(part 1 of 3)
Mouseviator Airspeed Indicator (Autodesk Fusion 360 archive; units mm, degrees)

design "Mouseviator Airspeed Indicator" references "X27.168 Stepper", "Instrument Bezel and Glass MS33638C"
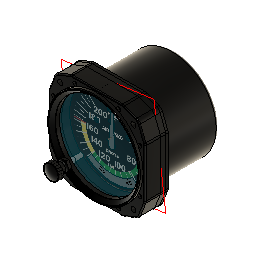
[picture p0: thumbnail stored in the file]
description: Spur Gear; Module: 2.0; Num Teeth: 30; Pressure Angle: 20.0; Backlash: 0.00 mm
parameter "NeedleFit" = 0.1
parameter "RotateTol" = 0.2
parameter "PressFit" = 0.1
parameter "KnobRodThick" = 4
parameter "ElephantFoot" = 0.5
parameter "GearGrow" = 0.15
external_derived "ExternalDerived1" bodies "Airspeed Bezel"
component_insert "Component Insert"
base_feature "Base Feature1"
position "Position1"
remove_instance "RemoveInstance10"
sketch "Sketch3" plane through (0, 2, 0) normal (0, 1, 0) x axis (-1, 0, 0)
  line L1 (41.1157, 22.3885) -> (36.4994, 34.1766)
  line L2 (41.4655, -20.5361) -> (41.4655, 20.5361)
  line L3 (36.4994, -34.1766) -> (41.1157, -22.3885)
  line L4 (23.2139, -41.1177) -> (33.6166, -37.0564)
  line L5 (-21.3665, -41.4655) -> (21.3665, -41.4655)
  line L6 (-33.6166, -37.0564) -> (-23.2139, -41.1177)
  line L7 (-41.1157, -22.3885) -> (-36.4994, -34.1766)
  line L8 (-41.4655, 20.5361) -> (-41.4655, -20.5361)
  line L9 (-36.4994, 34.1766) -> (-41.1157, 22.3885)
  line L10 (-23.2139, 41.1177) -> (-33.6166, 37.0564)
  line L11 (21.3665, 41.4655) -> (-21.3665, 41.4655)
  line L12 (33.6166, 37.0564) -> (23.2139, 41.1177)
  circle C1 centre (0, 0) radius 2.4
  circle C2 centre (-36.96, 18.76) radius 0.9
  circle C3 centre (-18.76, -36.96) radius 0.9
  circle C4 centre (36.96, -18.76) radius 0.9
  circle C5 centre (18.76, 36.96) radius 0.9
  circle C6 centre (36.96, 18.76) radius 0.9
  circle C7 centre (18.76, -36.96) radius 0.9
  circle C8 centre (-36.96, -18.76) radius 0.9
  circle C9 centre (-18.76, 36.96) radius 0.9
  arc A1 centre (36.3855, 20.5361) radius 5.08 clockwise from (41.1157, 22.3885) to (41.4655, 20.5361)
  arc A2 centre (36.3855, -20.5361) radius 5.08 clockwise from (41.4655, -20.5361) to (41.1157, -22.3885)
  arc A3 centre (31.7692, -32.3242) radius 5.08 clockwise from (36.4994, -34.1766) to (33.6166, -37.0564)
  arc A4 centre (21.3665, -36.3855) radius 5.08 clockwise from (23.2139, -41.1177) to (21.3665, -41.4655)
  arc A5 centre (-21.3665, -36.3855) radius 5.08 clockwise from (-21.3665, -41.4655) to (-23.2139, -41.1177)
  arc A6 centre (-31.7692, -32.3242) radius 5.08 clockwise from (-33.6166, -37.0564) to (-36.4994, -34.1766)
  arc A7 centre (-36.3855, -20.5361) radius 5.08 clockwise from (-41.1157, -22.3885) to (-41.4655, -20.5361)
  arc A8 centre (-36.3855, 20.5361) radius 5.08 clockwise from (-41.4655, 20.5361) to (-41.1157, 22.3885)
  arc A9 centre (-31.7692, 32.3242) radius 5.08 clockwise from (-36.4994, 34.1766) to (-33.6166, 37.0564)
  arc A10 centre (-21.3665, 36.3855) radius 5.08 clockwise from (-23.2139, 41.1177) to (-21.3665, 41.4655)
  arc A11 centre (21.3665, 36.3855) radius 5.08 clockwise from (21.3665, 41.4655) to (23.2139, 41.1177)
  arc A12 centre (31.7692, 32.3242) radius 5.08 clockwise from (33.6166, 37.0564) to (36.4994, 34.1766)
  circle C10 centre (-31.4309, 31.4309) radius 2.159
  circle C11 centre (31.4309, -31.4309) radius 2.159
  circle C12 centre (31.4309, 31.4309) radius 2.159
  circle C13 centre (-31.4309, -31.4309) radius 2.159
  circle C14 centre (0, 0) radius 35.5256
  concentric C1 C14
  dimension "d246" diameter C1 = 4.8
extrude "Extrude1" new body sketch "Sketch3" along normal blind 4.5
decal "Decal1"
decal "Decal2"
sketch "Sketch2" plane through (0, 2, 0) normal (0, -1, 0) x axis (1, 0, 0)
  line L1 (-41.129, -18.2913) -> (-41.129, 18.2913)
  line L2 (-36.3113, -33.5274) -> (-40.8669, -19.9021)
  line L3 (-19.078, -41.1949) -> (-33.0328, -36.7577)
  line L4 (17.5387, -41.4337) -> (-17.5387, -41.4337)
  line L5 (33.0328, -36.7577) -> (19.078, -41.1949)
  line L6 (40.8669, -19.9021) -> (36.3113, -33.5274)
  line L7 (41.129, 18.2913) -> (41.129, -18.2913)
  line L8 (36.3113, 33.5274) -> (40.8669, 19.9021)
  line L9 (19.078, 41.1949) -> (33.0328, 36.7577)
  line L10 (-17.5387, 41.4337) -> (17.5387, 41.4337)
  line L11 (-33.0328, 36.7577) -> (-19.078, 41.1949)
  line L12 (-40.8669, 19.9021) -> (-36.3113, 33.5274)
  line L13 (-9, 5.3277) -> (-9, 3.4858)
  line L14 (-9, 5.3393) -> (-9, 3.4741)
  line L15 (-41.4655, -20.5361) -> (-41.4655, 20.5361)
  line L16 (-36.4994, -34.1766) -> (-41.1157, -22.3885)
  line L17 (-23.2139, -41.1177) -> (-33.6166, -37.0564)
  line L18 (21.3665, -41.4655) -> (-21.3665, -41.4655)
  line L19 (33.6166, -37.0564) -> (23.2139, -41.1177)
  line L20 (41.1157, -22.3885) -> (36.4994, -34.1766)
  line L21 (41.4655, 20.5361) -> (41.4655, -20.5361)
  line L22 (36.4994, 34.1766) -> (41.1157, 22.3885)
  line L23 (23.2139, 41.1177) -> (33.6166, 37.0564)
  line L24 (-21.3665, 41.4655) -> (21.3665, 41.4655)
  line L25 (-33.6166, 37.0564) -> (-23.2139, 41.1177)
  line L26 (-41.1157, 22.3885) -> (-36.4994, 34.1766)
  circle C1 centre (-31.4309, -31.4309) radius 2.159
  circle C2 centre (-31.4309, 31.4309) radius 2.159
  circle C3 centre (31.4309, 31.4309) radius 2.159
  circle C4 centre (0, 0) radius 1.25
  circle C5 centre (31.4309, -31.4309) radius 2.159
  arc A1 centre (-36.049, 18.2913) radius 5.08 clockwise from (-41.129, 18.2913) to (-40.8669, 19.9021)
  arc A2 centre (-36.049, -18.2913) radius 5.08 clockwise from (-40.8669, -19.9021) to (-41.129, -18.2913)
  arc A3 centre (-31.4935, -31.9166) radius 5.08 clockwise from (-33.0328, -36.7577) to (-36.3113, -33.5274)
  arc A4 centre (-17.5387, -36.3537) radius 5.08 clockwise from (-17.5387, -41.4337) to (-19.078, -41.1949)
  arc A5 centre (17.5387, -36.3537) radius 5.08 clockwise from (19.078, -41.1949) to (17.5387, -41.4337)
  arc A6 centre (31.4935, -31.9166) radius 5.08 clockwise from (36.3113, -33.5274) to (33.0328, -36.7577)
  arc A7 centre (36.049, -18.2913) radius 5.08 clockwise from (41.129, -18.2913) to (40.8669, -19.9021)
  arc A8 centre (36.049, 18.2913) radius 5.08 clockwise from (40.8669, 19.9021) to (41.129, 18.2913)
  arc A9 centre (31.4935, 31.9166) radius 5.08 clockwise from (33.0328, 36.7577) to (36.3113, 33.5274)
  arc A10 centre (17.5387, 36.3537) radius 5.08 clockwise from (17.5387, 41.4337) to (19.078, 41.1949)
  arc A11 centre (-17.5387, 36.3537) radius 5.08 clockwise from (-19.078, 41.1949) to (-17.5387, 41.4337)
  arc A12 centre (-31.4935, 31.9166) radius 5.08 clockwise from (-36.3113, 33.5274) to (-33.0328, 36.7577)
  circle C6 centre (-2.3097, 10.9434) radius 1
  circle C7 centre (-18.76, 36.96) radius 0.9
  circle C8 centre (31.4309, -31.4309) radius 2.159
  circle C9 centre (-31.4309, 31.4309) radius 2.159
  circle C10 centre (31.4309, 31.4309) radius 2.159
  circle C11 centre (36.96, -18.76) radius 0.9
  circle C12 centre (-36.96, 18.76) radius 0.9
  circle C13 centre (-18.76, -36.96) radius 0.9
  circle C14 centre (18.76, -36.96) radius 0.9
  circle C15 centre (-31.4309, -31.4309) radius 2.159
  circle C16 centre (36.96, 18.76) radius 0.9
  circle C17 centre (-36.96, -18.76) radius 0.9
  circle C18 centre (18.76, 36.96) radius 0.9
  arc A13 centre (-36.3855, 20.5361) radius 5.08 clockwise from (-41.4655, 20.5361) to (-41.1157, 22.3885)
  arc A14 centre (-36.3855, -20.5361) radius 5.08 clockwise from (-41.1157, -22.3885) to (-41.4655, -20.5361)
  arc A15 centre (-31.7692, -32.3242) radius 5.08 clockwise from (-33.6166, -37.0564) to (-36.4994, -34.1766)
  arc A16 centre (-21.3665, -36.3855) radius 5.08 clockwise from (-21.3665, -41.4655) to (-23.2139, -41.1177)
  arc A17 centre (21.3665, -36.3855) radius 5.08 clockwise from (23.2139, -41.1177) to (21.3665, -41.4655)
  arc A18 centre (31.7692, -32.3242) radius 5.08 clockwise from (36.4994, -34.1766) to (33.6166, -37.0564)
  arc A19 centre (36.3855, -20.5361) radius 5.08 clockwise from (41.4655, -20.5361) to (41.1157, -22.3885)
  arc A20 centre (36.3855, 20.5361) radius 5.08 clockwise from (41.1157, 22.3885) to (41.4655, 20.5361)
  arc A21 centre (31.7692, 32.3242) radius 5.08 clockwise from (33.6166, 37.0564) to (36.4994, 34.1766)
  arc A22 centre (21.3665, 36.3855) radius 5.08 clockwise from (21.3665, 41.4655) to (23.2139, 41.1177)
  arc A23 centre (-21.3665, 36.3855) radius 5.08 clockwise from (-23.2139, 41.1177) to (-21.3665, 41.4655)
  arc A24 centre (-31.7692, 32.3242) radius 5.08 clockwise from (-36.4994, 34.1766) to (-33.6166, 37.0564)
  circle C19 centre (0, 0) radius 2.4
  dimension "d43" diameter C6 = 2
position "Position8"
joint "Assemble2" alignAngle 0 alignOffsetX 0 alignOffsetY 0 alignOffsetZ 0
base_feature "Base Feature1"
joint "Assemble4" alignAngle -90 alignOffsetX 0 alignOffsetY 0 alignOffsetZ -0.4
work_plane "WorkPlane1" AlongDistance 1.5
canvas "Canvas1"
sketch "Sketch1" plane through (0, 0.5, 0) normal (0, -1, 0) x axis (-1, 0, 0)
  line L1 (-6.6247, 4.1349) -> (-5.7667, 7.3554)
  line L2 (17.0612, -22.1649) -> (-6.6247, 4.1349)
  line L3 (17.2564, -22.0118) -> (-6.5518, 8.3569)
  line L4 (-2.4344, 7.42) -> (-5.7667, 7.3554)
  line L5 (17.4516, -21.8588) -> (-2.4344, 7.42)
  line L6 (17.4516, -21.8588) -> (17.0612, -22.1649)
  line L7 (-2.0946, -0.8951) -> (-1.3853, 1.7668)
  line L8 (1.3689, 1.8201) -> (-1.3853, 1.7668)
  circle C1 centre (0, 0) radius 0.5
  circle C2 centre (0, 0) radius 0.55
  point P3 (-6.6247, 4.1349)
  point P6 (-2.4344, 7.42)
  point P4 (17.0612, -22.1649)
  point P7 (17.4516, -21.8588)
  point P5 (17.2564, -22.0118)
  point P9 (-1.3853, 1.7668)
  point P10 (-2.0946, -0.8951)
  point P11 (-1.3853, 1.7668)
  point P12 (1.3689, 1.8201)
  point P14 (-5.7667, 7.3554)
  symmetric P3 L3 P6
  symmetric P4 L3 P7
  midpoint P5 L6
  perpendicular L3 L6
  coincident L3 P9
  coincident L2 P10
  parallel L1 L7
  symmetric L3 P9 P11
  symmetric L3 P10 P12
  concentric C1 C2
  coincident L3 P14
  dimension "d55" distance C1 C2 = 0.05 (= "NeedleFit / 2")
extrude "Extrude1" new body sketch "Sketch1" profile of L1 L2 L4 L5 L6 C1 L7 L8 C2 along normal blind 1
extrude "Extrude2" cut sketch "Sketch2" profile of C6 to an object
fillet "Fillet1" radius 0.5 0.25
decal "Decal3"
copy_paste "CutPaste3"
copy_paste "CutPaste4"
sketch "Sketch2" plane through (0, 0.5, 0) normal (0, 1, 0) x axis (-1, 0, 0)
  line L1 (-5.7667, -7.3554) -> (-6.6247, -4.1349)
  line L2 (-2.4344, -7.42) -> (-5.7667, -7.3554)
  line L3 (17.4516, 21.8588) -> (-2.4344, -7.42)
  line L4 (17.0612, 22.1649) -> (17.4516, 21.8588)
  line L5 (-6.6247, -4.1349) -> (17.0612, 22.1649)
  circle C1 centre (0, 0) radius 2
  circle C2 centre (0, 0) radius 0.8
  circle C3 centre (0, 0) radius 0.5
  point P1 (0, 0)
  point P7 (0, 0)
  coincident P1 P7
  concentric C1 C2
  dimension "d51" diameter C1 = 4
  dimension "d266" distance C2 C3 = 0.3
extrude "Extrude2" add sketch "Sketch2" profile of C1 C2 to an object
ground "Ground1"
canvas "Canvas1"
position "Position4"
sketch "Window" plane through (0, 2, 0) normal (0, -1, 0) x axis (1, 0, 0)
  line L1 (22.1762, -26.4285) -> (17.6767, -21.0662)
  line L2 (0, -34.5) -> (0, -27.5)
  line L3 (-22.1762, -26.4285) -> (-17.6767, -21.0662)
  line L4 (-5.1952, 24.4031) -> (-3.7897, 17.8011)
  line L5 (6.9993, 23.9481) -> (5.1057, 17.4692)
  line L6 (-41.4655, -20.5361) -> (-41.4655, 20.5361)
  line L7 (-36.4994, -34.1766) -> (-41.1157, -22.3885)
  line L8 (-23.2139, -41.1177) -> (-33.6166, -37.0564)
  line L9 (21.3665, -41.4655) -> (-21.3665, -41.4655)
  line L10 (33.6166, -37.0564) -> (23.2139, -41.1177)
  line L11 (41.1157, -22.3885) -> (36.4994, -34.1766)
  line L12 (41.4655, 20.5361) -> (41.4655, -20.5361)
  line L13 (36.4994, 34.1766) -> (41.1157, 22.3885)
  line L14 (23.2139, 41.1177) -> (33.6166, 37.0564)
  line L15 (-21.3665, 41.4655) -> (21.3665, 41.4655)
  line L16 (-33.6166, 37.0564) -> (-23.2139, 41.1177)
  line L17 (-41.1157, 22.3885) -> (-36.4994, 34.1766)
  arc A1 centre (0, 0) radius 27.5 clockwise from (17.6767, -21.0662) to (0, -27.5)
  arc A2 centre (0, 0) radius 34.5 clockwise from (22.1762, -26.4285) to (0, -34.5)
  arc A3 centre (0, 0) radius 27.5 clockwise from (0, -27.5) to (-17.6767, -21.0662)
  arc A4 centre (0, 0) radius 34.5 clockwise from (0, -34.5) to (-22.1762, -26.4285)
  arc A5 centre (0, 0) radius 18.2 clockwise from (-3.7897, 17.8011) to (5.1057, 17.4692)
  arc A6 centre (0, 0) radius 24.95 clockwise from (-5.1952, 24.4031) to (6.9993, 23.9481)
  circle C1 centre (-18.76, 36.96) radius 0.9
  circle C2 centre (31.4309, -31.4309) radius 2.159
  circle C3 centre (-31.4309, 31.4309) radius 2.159
  circle C4 centre (31.4309, 31.4309) radius 2.159
  circle C5 centre (36.96, -18.76) radius 0.9
  circle C6 centre (-36.96, 18.76) radius 0.9
  circle C7 centre (-18.76, -36.96) radius 0.9
  circle C8 centre (18.76, -36.96) radius 0.9
  circle C9 centre (-31.4309, -31.4309) radius 2.159
  circle C10 centre (36.96, 18.76) radius 0.9
  circle C11 centre (-36.96, -18.76) radius 0.9
  circle C12 centre (18.76, 36.96) radius 0.9
  arc A7 centre (-36.3855, 20.5361) radius 5.08 clockwise from (-41.4655, 20.5361) to (-41.1157, 22.3885)
  arc A8 centre (-36.3855, -20.5361) radius 5.08 clockwise from (-41.1157, -22.3885) to (-41.4655, -20.5361)
  arc A9 centre (-31.7692, -32.3242) radius 5.08 clockwise from (-33.6166, -37.0564) to (-36.4994, -34.1766)
  arc A10 centre (-21.3665, -36.3855) radius 5.08 clockwise from (-21.3665, -41.4655) to (-23.2139, -41.1177)
  arc A11 centre (21.3665, -36.3855) radius 5.08 clockwise from (23.2139, -41.1177) to (21.3665, -41.4655)
  arc A12 centre (31.7692, -32.3242) radius 5.08 clockwise from (36.4994, -34.1766) to (33.6166, -37.0564)
  arc A13 centre (36.3855, -20.5361) radius 5.08 clockwise from (41.4655, -20.5361) to (41.1157, -22.3885)
  arc A14 centre (36.3855, 20.5361) radius 5.08 clockwise from (41.1157, 22.3885) to (41.4655, 20.5361)
  arc A15 centre (31.7692, 32.3242) radius 5.08 clockwise from (33.6166, 37.0564) to (36.4994, 34.1766)
  arc A16 centre (21.3665, 36.3855) radius 5.08 clockwise from (21.3665, 41.4655) to (23.2139, 41.1177)
  arc A17 centre (-21.3665, 36.3855) radius 5.08 clockwise from (-23.2139, 41.1177) to (-21.3665, 41.4655)
  arc A18 centre (-31.7692, 32.3242) radius 5.08 clockwise from (-36.4994, 34.1766) to (-33.6166, 37.0564)
  circle C13 centre (-2.3097, 10.9434) radius 1
  circle C14 centre (0, 0) radius 2.4
  point P3 (0, -27.5)
  point P9 (0, -27.5)
  point P4 (17.6767, -21.0662)
  point P10 (-17.6767, -21.0662)
  point P6 (22.1762, -26.4285)
  point P11 (-22.1762, -26.4285)
  point P7 (0, -34.5)
  point P13 (0, -34.5)
  point P2 (0, 0)
  point P14 (0, 0)
  point P12 (0, 0)
  point P20 (0, 18.2)
  vertical L2
  symmetric P3 L2 P9
  symmetric P4 L2 P10
  symmetric A1 L2 A3
  symmetric P6 L2 P11
  symmetric P7 L2 P13
  symmetric A2 L2 A4
  coincident P2 P14
  vertical P12 P20
  dimension "d64" = 7
  dimension "d65" radius A1 = 27.5
  dimension "d66" angle P2 P3 P4 = 40
  dimension "d146" radius A5 = 18.2
  dimension "d147" = 6.75
extrude "Extrude3" cut sketch "Window" profile of A1 A2 L1 A3 L3 A4 A5 L4 A6 L5 to an object
sketch "Carved out wheel" plane through (0, 6.5, 0) normal (0, 1, 0) x axis (-1, 0, 0)
  line L1 (36.4994, 34.1766) -> (41.1157, 22.3885)
  line L2 (23.2139, 41.1177) -> (33.6166, 37.0564)
  line L3 (-21.3665, 41.4655) -> (21.3665, 41.4655)
  line L4 (-33.6166, 37.0564) -> (-23.2139, 41.1177)
  line L5 (-41.1157, 22.3885) -> (-36.4994, 34.1766)
  line L6 (-41.4655, -20.5361) -> (-41.4655, 20.5361)
  line L7 (-36.4994, -34.1766) -> (-41.1157, -22.3885)
  line L8 (-23.2139, -41.1177) -> (-33.6166, -37.0564)
  line L9 (21.3665, -41.4655) -> (-21.3665, -41.4655)
  line L10 (33.6166, -37.0564) -> (23.2139, -41.1177)
  line L11 (41.1157, -22.3885) -> (36.4994, -34.1766)
  line L12 (41.4655, 20.5361) -> (41.4655, -20.5361)
  line L13 (22.1762, -26.4285) -> (17.6767, -21.0662)
  line L14 (-17.6767, -21.0662) -> (-22.1762, -26.4285)
  line L15 (3.7897, 17.8011) -> (5.1952, 24.4031)
  line L16 (-6.9993, 23.9481) -> (-5.1057, 17.4692)
  circle C1 centre (0, 0) radius 27.5
  circle C2 centre (0, 0) radius 34.5
  circle C3 centre (0, 0) radius 35
  circle C4 centre (0, 0) radius 18.2
  circle C5 centre (18.76, 36.96) radius 0.9
  circle C6 centre (-31.4309, -31.4309) radius 2.159
  circle C7 centre (31.4309, 31.4309) radius 2.159
  circle C8 centre (-31.4309, 31.4309) radius 2.159
  circle C9 centre (-36.96, -18.76) radius 0.9
  circle C10 centre (36.96, 18.76) radius 0.9
  circle C11 centre (18.76, -36.96) radius 0.9
  circle C12 centre (-18.76, -36.96) radius 0.9
  circle C13 centre (31.4309, -31.4309) radius 2.159
  circle C14 centre (-36.96, 18.76) radius 0.9
  circle C15 centre (36.96, -18.76) radius 0.9
  circle C16 centre (-18.76, 36.96) radius 0.9
  arc A1 centre (36.3855, 20.5361) radius 5.08 clockwise from (41.1157, 22.3885) to (41.4655, 20.5361)
  arc A2 centre (31.7692, 32.3242) radius 5.08 clockwise from (33.6166, 37.0564) to (36.4994, 34.1766)
  arc A3 centre (21.3665, 36.3855) radius 5.08 clockwise from (21.3665, 41.4655) to (23.2139, 41.1177)
  arc A4 centre (-21.3665, 36.3855) radius 5.08 clockwise from (-23.2139, 41.1177) to (-21.3665, 41.4655)
  arc A5 centre (-31.7692, 32.3242) radius 5.08 clockwise from (-36.4994, 34.1766) to (-33.6166, 37.0564)
  arc A6 centre (-36.3855, 20.5361) radius 5.08 clockwise from (-41.4655, 20.5361) to (-41.1157, 22.3885)
  arc A7 centre (-36.3855, -20.5361) radius 5.08 clockwise from (-41.1157, -22.3885) to (-41.4655, -20.5361)
  arc A8 centre (-31.7692, -32.3242) radius 5.08 clockwise from (-33.6166, -37.0564) to (-36.4994, -34.1766)
  arc A9 centre (-21.3665, -36.3855) radius 5.08 clockwise from (-21.3665, -41.4655) to (-23.2139, -41.1177)
  arc A10 centre (21.3665, -36.3855) radius 5.08 clockwise from (23.2139, -41.1177) to (21.3665, -41.4655)
  arc A11 centre (31.7692, -32.3242) radius 5.08 clockwise from (36.4994, -34.1766) to (33.6166, -37.0564)
  arc A12 centre (36.3855, -20.5361) radius 5.08 clockwise from (41.4655, -20.5361) to (41.1157, -22.3885)
  arc A13 centre (0, 0) radius 27.5 clockwise from (17.6767, -21.0662) to (-17.6767, -21.0662)
  arc A14 centre (0, 0) radius 34.5 clockwise from (22.1762, -26.4285) to (-22.1762, -26.4285)
  arc A15 centre (0, 0) radius 18.2 clockwise from (-5.1057, 17.4692) to (3.7897, 17.8011)
  arc A16 centre (0, 0) radius 24.95 clockwise from (-6.9993, 23.9481) to (5.1952, 24.4031)
  circle C17 centre (2.3097, 10.9434) radius 1
  circle C18 centre (0, 0) radius 2.4
  point P1 (0, 0)
  point P2 (0, 0)
  coincident P1 P2
  dimension "d88" diameter C3 = 70
extrude "Extrude4" cut sketch "Carved out wheel" profile of C1 C2 C3 C4 A13 L13 A14 L14 L15 L16 A16 to an object offset -1
joint "Assemble8" alignAngle 270 alignOffsetX 0 alignOffsetY 0 alignOffsetZ 0
joint "Assemble7" alignAngle 90 alignOffsetX 0 alignOffsetY 0 alignOffsetZ -2
sketch "Sketch1" plane through (0, 3, 0) normal (0, 1, 0) x axis (-1, 0, 0)
  line L1 (-6.9993, 23.9481) -> (-5.1057, 17.4692)
  line L2 (3.7897, 17.8011) -> (5.1952, 24.4031)
  line L3 (-17.6767, -21.0662) -> (-22.1762, -26.4285)
  line L4 (22.1762, -26.4285) -> (17.6767, -21.0662)
  arc A1 centre (0, 0) radius 34.5 clockwise from (22.1762, -26.4285) to (-22.1762, -26.4285)
  circle C1 centre (0, 0) radius 18.7
  circle C2 centre (0, 0) radius 35
  circle C3 centre (0, 0) radius 34.5
  arc A2 centre (0, 0) radius 24.95 clockwise from (-6.9993, 23.9481) to (5.1952, 24.4031)
  arc A3 centre (0, 0) radius 18.2 clockwise from (3.7897, 17.8011) to (-5.1057, 17.4692)
extrude "Extrude1" new body sketch "Sketch1" profile of A1 C1 C3 along normal blind 1
sketch "Sketch1" plane through (0, 0, 0) normal (0, 0, 1) x axis (1, 0, 0)
  circle C1 centre (0, 0) radius 27.5492
extrude "Extrude1" new body sketch "Sketch1" along normal blind 12.7
sketch "Sketch2" plane through (0, 0, 0) normal (0, 0, 1) x axis (1, 0, 0)
  curve K1 (31.9915, -0.7373) -> (28.127, -1.8948)
  curve K2 (31.9915, 0.7373) -> (28.127, 1.8948)
  line L1 (28.127, -1.8948) -> (27.4769, -1.8517)
  line L2 (28.127, 1.8948) -> (27.4769, 1.8517)
  line L3 (27.4769, 1.8517) -> (27.4769, -1.8517)
  arc A1 centre (0, 0) radius 32 clockwise from (31.9915, 0.7373) to (31.9915, -0.7373)
extrude "Extrude2" add sketch "Sketch2" along normal blind 12.7
fillet "Fillet1" radius 1
circular_pattern "C-Pattern1" countU 30 TotalAngle 360
sketch "Sketch3" plane through (0, 0, 0) normal (0, 0, 1) x axis (1, 0, 0)
  circle C1 centre (0, 0) radius 30
copy_paste "CutPaste1"
joint "Assemble1" alignAngle 0 alignOffsetX 0 alignOffsetY 0 alignOffsetZ 0
sketch "Sketch3" plane through (0, 4, 0) normal (0, -1, 0) x axis (1, 0, 0)
  curve K1 (27.4076, -2.7893) -> (28.3353, -1.8928)
  curve K2 (31.9915, -0.7373) -> (28.3353, -1.8928)
  curve K3 (31.9915, 0.7373) -> (28.3353, 1.8928)
  curve K4 (28.3353, 1.8928) -> (27.4076, 2.7893)
  curve K5 (27.3886, 2.97) -> (28.1096, 4.0398)
  curve K6 (31.4457, 5.9302) -> (28.1096, 4.0398)
  curve K7 (31.1391, 7.3726) -> (27.3226, 7.7427)
  curve K8 (27.3226, 7.7427) -> (26.2288, 8.4267)
  curve K9 (26.1726, 8.5996) -> (26.6554, 9.7959)
  curve K10 (29.5256, 12.3385) -> (26.6554, 9.7959)
  curve K11 (28.9258, 13.6857) -> (25.1157, 13.2541)
  curve K12 (25.1157, 13.2541) -> (23.9036, 13.6958)
  curve K13 (23.8127, 13.8532) -> (24.0363, 15.1238)
  curve K14 (26.3151, 18.2076) -> (24.0363, 15.1238)
  curve K15 (25.4483, 19.4007) -> (21.8112, 18.1864)
  curve K16 (21.8112, 18.1864) -> (20.5337, 18.3664)
  curve K17 (20.4121, 18.5015) -> (20.3666, 19.7907)
  curve K18 (21.9544, 23.2809) -> (20.3666, 19.7907)
  curve K19 (20.8585, 24.2677) -> (17.5534, 22.3237)
  curve K20 (17.5534, 22.3237) -> (16.2665, 22.2342)
  curve K21 (16.1194, 22.3411) -> (15.8068, 23.5927)
  curve K22 (16.6343, 27.3368) -> (15.8068, 23.5927)
  curve K23 (15.3572, 28.0741) -> (12.5284, 25.4855)
  curve K24 (12.5284, 25.4855) -> (11.2882, 25.1303)
  curve K25 (11.1222, 25.2043) -> (10.5562, 26.3636)
  curve K26 (10.5872, 30.1979) -> (10.5562, 26.3636)
  curve K27 (9.1847, 30.6536) -> (6.9559, 27.5334)
  curve K28 (6.9559, 27.5334) -> (5.8167, 26.9281)
  curve K29 (5.6389, 26.9659) -> (4.8443, 27.9822)
  curve K30 (4.0773, 31.7392) -> (4.8443, 27.9822)
  curve K31 (2.6107, 31.8933) -> (1.0794, 28.3779)
  curve K32 (1.0794, 28.3779) -> (0.0909, 27.5491)
  curve K33 (-0.0909, 27.5491) -> (-1.0794, 28.3779)
  curve K34 (-2.6107, 31.8933) -> (-1.0794, 28.3779)
  curve K35 (-4.0773, 31.7392) -> (-4.8443, 27.9822)
  curve K36 (-4.8443, 27.9822) -> (-5.6389, 26.9659)
  curve K37 (-5.8167, 26.9281) -> (-6.9559, 27.5334)
  curve K38 (-9.1847, 30.6536) -> (-6.9559, 27.5334)
  curve K39 (-10.5872, 30.1979) -> (-10.5562, 26.3636)
  curve K40 (-10.5562, 26.3636) -> (-11.1222, 25.2043)
  curve K41 (-11.2882, 25.1303) -> (-12.5284, 25.4855)
  curve K42 (-15.3572, 28.0741) -> (-12.5284, 25.4855)
  curve K43 (-16.6343, 27.3368) -> (-15.8068, 23.5927)
  curve K44 (-15.8068, 23.5927) -> (-16.1194, 22.3411)
  curve K45 (-16.2665, 22.2342) -> (-17.5534, 22.3237)
  curve K46 (-20.8585, 24.2677) -> (-17.5534, 22.3237)
  curve K47 (-21.9544, 23.2809) -> (-20.3666, 19.7907)
  curve K48 (-20.3666, 19.7907) -> (-20.4121, 18.5015)
  curve K49 (-20.5337, 18.3664) -> (-21.8112, 18.1864)
  curve K50 (-25.4483, 19.4007) -> (-21.8112, 18.1864)
  curve K51 (-26.3151, 18.2076) -> (-24.0363, 15.1238)
  curve K52 (-24.0363, 15.1238) -> (-23.8127, 13.8532)
  curve K53 (-23.9036, 13.6958) -> (-25.1157, 13.2541)
  curve K54 (-28.9258, 13.6857) -> (-25.1157, 13.2541)
  curve K55 (-29.5256, 12.3385) -> (-26.6554, 9.7959)
  curve K56 (-26.6554, 9.7959) -> (-26.1726, 8.5996)
  curve K57 (-26.2288, 8.4267) -> (-27.3226, 7.7427)
  curve K58 (-31.1391, 7.3726) -> (-27.3226, 7.7427)
  curve K59 (-31.4457, 5.9302) -> (-28.1096, 4.0398)
  curve K60 (-28.1096, 4.0398) -> (-27.3886, 2.97)
  curve K61 (-27.4076, 2.7893) -> (-28.3353, 1.8928)
  curve K62 (-31.9915, 0.7373) -> (-28.3353, 1.8928)
  curve K63 (-31.9915, -0.7373) -> (-28.3353, -1.8928)
  curve K64 (-28.3353, -1.8928) -> (-27.4076, -2.7893)
  curve K65 (-27.3886, -2.97) -> (-28.1096, -4.0398)
  curve K66 (-31.4457, -5.9302) -> (-28.1096, -4.0398)
  curve K67 (-31.1391, -7.3726) -> (-27.3226, -7.7427)
  curve K68 (-27.3226, -7.7427) -> (-26.2288, -8.4267)
  curve K69 (-26.1726, -8.5996) -> (-26.6554, -9.7959)
  curve K70 (-29.5256, -12.3385) -> (-26.6554, -9.7959)
  curve K71 (-28.9258, -13.6857) -> (-25.1157, -13.2541)
  curve K72 (-25.1157, -13.2541) -> (-23.9036, -13.6958)
  curve K73 (-23.8127, -13.8532) -> (-24.0363, -15.1238)
  curve K74 (-26.3151, -18.2076) -> (-24.0363, -15.1238)
  curve K75 (-25.4483, -19.4007) -> (-21.8112, -18.1864)
  curve K76 (-21.8112, -18.1864) -> (-20.5337, -18.3664)
  curve K77 (-20.4121, -18.5015) -> (-20.3666, -19.7907)
  curve K78 (-21.9544, -23.2809) -> (-20.3666, -19.7907)
  curve K79 (-20.8585, -24.2677) -> (-17.5534, -22.3237)
  curve K80 (-17.5534, -22.3237) -> (-16.2665, -22.2342)
  curve K81 (-16.1194, -22.3411) -> (-15.8068, -23.5927)
  curve K82 (-16.6343, -27.3368) -> (-15.8068, -23.5927)
  curve K83 (-15.3572, -28.0741) -> (-12.5284, -25.4855)
  curve K84 (-12.5284, -25.4855) -> (-11.2882, -25.1303)
  curve K85 (-11.1222, -25.2043) -> (-10.5562, -26.3636)
  curve K86 (-10.5872, -30.1979) -> (-10.5562, -26.3636)
  curve K87 (-9.1847, -30.6536) -> (-6.9559, -27.5334)
  curve K88 (-6.9559, -27.5334) -> (-5.8167, -26.9281)
  curve K89 (-5.6389, -26.9659) -> (-4.8443, -27.9822)
  curve K90 (-4.0773, -31.7392) -> (-4.8443, -27.9822)
  curve K91 (-2.6107, -31.8933) -> (-1.0794, -28.3779)
  curve K92 (-1.0794, -28.3779) -> (-0.0909, -27.5491)
  curve K93 (0.0909, -27.5491) -> (1.0794, -28.3779)
  curve K94 (2.6107, -31.8933) -> (1.0794, -28.3779)
  curve K95 (4.0773, -31.7392) -> (4.8443, -27.9822)
  curve K96 (4.8443, -27.9822) -> (5.6389, -26.9659)
  curve K97 (5.8167, -26.9281) -> (6.9559, -27.5334)
  curve K98 (9.1847, -30.6536) -> (6.9559, -27.5334)
  curve K99 (10.5872, -30.1979) -> (10.5562, -26.3636)
  curve K100 (10.5562, -26.3636) -> (11.1222, -25.2043)
  curve K101 (11.2882, -25.1303) -> (12.5284, -25.4855)
  curve K102 (15.3572, -28.0741) -> (12.5284, -25.4855)
  curve K103 (16.6343, -27.3368) -> (15.8068, -23.5927)
  curve K104 (15.8068, -23.5927) -> (16.1194, -22.3411)
  curve K105 (16.2665, -22.2342) -> (17.5534, -22.3237)
  curve K106 (20.8585, -24.2677) -> (17.5534, -22.3237)
  curve K107 (21.9544, -23.2809) -> (20.3666, -19.7907)
  curve K108 (20.3666, -19.7907) -> (20.4121, -18.5015)
  curve K109 (20.5337, -18.3664) -> (21.8112, -18.1864)
  curve K110 (25.4483, -19.4007) -> (21.8112, -18.1864)
  curve K111 (26.3151, -18.2076) -> (24.0363, -15.1238)
  curve K112 (24.0363, -15.1238) -> (23.8127, -13.8532)
  curve K113 (23.9036, -13.6958) -> (25.1157, -13.2541)
  curve K114 (28.9258, -13.6857) -> (25.1157, -13.2541)
  curve K115 (29.5256, -12.3385) -> (26.6554, -9.7959)
  curve K116 (26.6554, -9.7959) -> (26.1726, -8.5996)
  curve K117 (26.2288, -8.4267) -> (27.3226, -7.7427)
  curve K118 (31.1391, -7.3726) -> (27.3226, -7.7427)
  curve K119 (31.4457, -5.9302) -> (28.1096, -4.0398)
  curve K120 (28.1096, -4.0398) -> (27.3886, -2.97)
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extrude "Extrude4" cut sketch "Sketch3" to an object
sketch "Carved out knob" plane through (0, 6.5, 0) normal (0, 1, 0) x axis (-1, 0, 0)
  line L1 (0, -17.0687) -> (0, 0)
  line L2 (64.1104, -64.1104) -> (0, 0)
  line L3 (36.4994, 34.1766) -> (41.1157, 22.3885)
  line L4 (23.2139, 41.1177) -> (33.6166, 37.0564)
  line L5 (-21.3665, 41.4655) -> (21.3665, 41.4655)
  line L6 (-33.6166, 37.0564) -> (-23.2139, 41.1177)
  line L7 (-41.1157, 22.3885) -> (-36.4994, 34.1766)
  line L8 (-41.4655, -20.5361) -> (-41.4655, 20.5361)
  line L9 (-36.4994, -34.1766) -> (-41.1157, -22.3885)
  line L10 (-23.2139, -41.1177) -> (-33.6166, -37.0564)
  line L11 (21.3665, -41.4655) -> (-21.3665, -41.4655)
  line L12 (33.6166, -37.0564) -> (23.2139, -41.1177)
  line L13 (41.1157, -22.3885) -> (36.4994, -34.1766)
  line L14 (41.4655, 20.5361) -> (41.4655, -20.5361)
  circle C1 centre (26.8701, -26.8701) radius 10
  circle C2 centre (2.3097, 10.9434) radius 1
  circle C3 centre (0, 0) radius 18.2
  arc A1 centre (36.3855, 20.5361) radius 5.08 clockwise from (41.1157, 22.3885) to (41.4655, 20.5361)
  arc A2 centre (31.7692, 32.3242) radius 5.08 clockwise from (33.6166, 37.0564) to (36.4994, 34.1766)
  arc A3 centre (21.3665, 36.3855) radius 5.08 clockwise from (21.3665, 41.4655) to (23.2139, 41.1177)
  arc A4 centre (-21.3665, 36.3855) radius 5.08 clockwise from (-23.2139, 41.1177) to (-21.3665, 41.4655)
  arc A5 centre (-31.7692, 32.3242) radius 5.08 clockwise from (-36.4994, 34.1766) to (-33.6166, 37.0564)
  arc A6 centre (-36.3855, 20.5361) radius 5.08 clockwise from (-41.4655, 20.5361) to (-41.1157, 22.3885)
  arc A7 centre (-36.3855, -20.5361) radius 5.08 clockwise from (-41.1157, -22.3885) to (-41.4655, -20.5361)
  arc A8 centre (-31.7692, -32.3242) radius 5.08 clockwise from (-33.6166, -37.0564) to (-36.4994, -34.1766)
  arc A9 centre (-21.3665, -36.3855) radius 5.08 clockwise from (-21.3665, -41.4655) to (-23.2139, -41.1177)
  arc A10 centre (21.3665, -36.3855) radius 5.08 clockwise from (23.2139, -41.1177) to (21.3665, -41.4655)
  arc A11 centre (31.7692, -32.3242) radius 5.08 clockwise from (36.4994, -34.1766) to (33.6166, -37.0564)
  arc A12 centre (36.3855, -20.5361) radius 5.08 clockwise from (41.4655, -20.5361) to (41.1157, -22.3885)
  circle C4 centre (31.4309, 31.4309) radius 2.159
  circle C5 centre (-31.4309, -31.4309) radius 2.159
  circle C6 centre (-36.96, -18.76) radius 0.9
  circle C7 centre (-18.76, 36.96) radius 0.9
  circle C8 centre (-36.96, 18.76) radius 0.9
  circle C9 centre (36.96, -18.76) radius 0.9
  circle C10 centre (36.96, 18.76) radius 0.9
  circle C11 centre (31.4309, -31.4309) radius 2.159
  circle C12 centre (-18.76, -36.96) radius 0.9
  circle C13 centre (18.76, -36.96) radius 0.9
  circle C14 centre (-31.4309, 31.4309) radius 2.159
  circle C15 centre (18.76, 36.96) radius 0.9
  circle C16 centre (0, 0) radius 35
  circle C17 centre (0, 0) radius 2.4
  point P1 (0, 0)
  point P4 (0, 0)
  point P6 (0, 0)
  point P2 (26.8701, -26.8701)
  point P8 (0, 0)
  coincident P1 P4
  vertical L1
  coincident P1 P6
  coincident P2 L2
  coincident P4 P8
  dimension "d79" diameter C1 = 20
  dimension "d116" angle L1 L2 = 45
  dimension "d117" distance P2 P8 = 38
extrude "Extrude5" cut sketch "Carved out knob" profile of C1 to an object offset 1
sketch "Hole for knob" plane through (0, 4, 0) normal (0, 1, 0) x axis (-1, 0, 0)
  circle C1 centre (26.7653, -26.7653) radius 2.25
  arc A1 centre (26.8701, -26.8701) radius 10 clockwise from (30.3201, -17.484) to (17.484, -30.3201)
  arc A2 centre (0, 0) radius 35 clockwise from (30.3201, -17.484) to (17.484, -30.3201)
  circle C2 centre (31.4309, -31.4309) radius 2.159
  point P4 (26.7653, -26.7653)
  point P5 (26.7653, -26.7653)
  coincident P4 P5
  dimension "d80" diameter C1 = 4.5 (= "KnobRodThick + 0.5 mm")
extrude "Extrude6" cut sketch "Hole for knob" profile of C1 to an object
sketch "Sketch4" plane through (-27.748, 4, -27.7995) normal (0, 1, 0) x axis (-1, 0, 0)
  line L1 (4.4079, -3.2052) -> (4.3557, -3.1352)
  line L2 (7.1126, 2.1531) -> (6.9076, 2.2582)
  line L3 (4.7827, -3.9737) -> (4.7206, -3.8019)
  line L4 (7.5464, 1.8883) -> (7.326, 2.0302)
  line L5 (5.0029, -5.1016) -> (4.9764, -4.8408)
  line L6 (8.0029, 0.5245) -> (8.0029, 1.5439)
  line L7 (5.4078, 2.5933) -> (3.4863, 2.1245)
  line L8 (6.0468, -0.4893) -> (6.1939, -0.4552)
  line L9 (4.9395, -4.5973) -> (4.8938, -4.3715)
  line L10 (4.2445, -3.0109) -> (4.2268, -2.995)
  line L11 (5.9139, 2.5817) -> (5.7958, 2.5972)
  line L12 (4.7206, -3.8019) -> (4.6563, -3.648)
  line L13 (4.3101, -3.0801) -> (4.2727, -3.039)
  line L14 (6.9076, 2.2582) -> (6.7122, 2.3466)
  line L15 (5.6055, -0.5399) -> (5.6928, -0.5371)
  line L16 (6.7122, 2.3466) -> (6.5274, 2.4194)
  line L17 (4.9764, -4.8408) -> (4.9395, -4.5973)
  line L18 (5.0174, -5.3793) -> (5.0029, -5.1016)
  line L19 (7.7726, 0.3419) -> (8.0029, 0.5245)
  line L20 (6.7122, -0.2781) -> (6.9076, -0.1898)
  line L21 (6.5274, -0.3509) -> (6.7122, -0.2781)
  line L22 (5.4785, -0.535) -> (5.534, -0.5386)
  line L23 (8.0029, 1.5439) -> (7.7726, 1.7265)
  line L24 (5.6928, 2.6055) -> (5.6055, 2.6083)
  line L25 (7.1126, -0.0847) -> (7.326, 0.0383)
  line L26 (6.5274, 2.4194) -> (6.3543, 2.4779)
  line L27 (5.534, 2.6071) -> (5.4785, 2.6034)
  line L28 (4.2727, -3.039) -> (4.2445, -3.0109)
  line L29 (5.6055, 2.6083) -> (5.534, 2.6071)
  line L30 (5.4078, -0.5249) -> (5.4155, -0.5265)
  line L31 (5.7958, 2.5972) -> (5.6928, 2.6055)
  line L32 (5.4391, -0.5304) -> (5.4785, -0.535)
  line L33 (4.2207, -2.9899) -> (2.6561, -1.7799)
  line L34 (6.3543, 2.4779) -> (6.1939, 2.5236)
  line L35 (7.5464, 0.1801) -> (7.7726, 0.3419)
  line L36 (4.5913, -3.5118) -> (4.5272, -3.3929)
  line L37 (6.0468, 2.5577) -> (5.9139, 2.5817)
  line L38 (6.3543, -0.4095) -> (6.5274, -0.3509)
  line L39 (7.326, 0.0383) -> (7.5464, 0.1801)
  line L40 (7.326, 2.0302) -> (7.1126, 2.1531)
  line L41 (4.4656, -3.2909) -> (4.4079, -3.2052)
  line L42 (5.4155, 2.595) -> (5.4078, 2.5933)
  line L43 (6.1939, -0.4552) -> (6.3543, -0.4095)
  line L44 (5.9139, -0.5133) -> (6.0468, -0.4893)
  line L45 (4.841, -4.1636) -> (4.7827, -3.9737)
  line L46 (5.534, -0.5386) -> (5.6055, -0.5399)
  line L47 (5.4785, 2.6034) -> (5.4391, 2.5988)
  line L48 (7.7726, 1.7265) -> (7.5464, 1.8883)
  line L49 (5.4391, 2.5988) -> (5.4155, 2.595)
  line L50 (5.4155, -0.5265) -> (5.4391, -0.5304)
  line L51 (6.1939, 2.5236) -> (6.0468, 2.5577)
  line L52 (2.6561, -1.7799) -> (3.4863, -0.0561)
  line L53 (3.4863, -0.0561) -> (5.4078, -0.5249)
  line L54 (3.6674, -6.1666) -> (3.9349, -6.2425)
  line L55 (5.6928, -0.5371) -> (5.7958, -0.5287)
  line L56 (-3.9502, -4.9158) -> (-3.9661, -4.9691)
  line L57 (-3.9832, -5.0385) -> (-4, -5.1242)
  line L58 (-1.0615, -6.158) -> (-1.0085, -6.0338)
  line L59 (-4.026, -5.3451) -> (-4.0321, -5.48)
  line L60 (-3.479, -7.6126) -> (-2.4852, -7.8395)
  line L61 (-0.9672, -5.922) -> (-0.9362, -5.8235)
  line L62 (4.6563, -3.648) -> (4.5913, -3.5118)
  line L63 (-3.928, -4.8562) -> (-3.937, -4.8783)
  line L64 (2.209, -5.4115) -> (2.3274, -5.5052)
  line L65 (-0.8846, -5.5429) -> (-0.9141, -3.5653)
  line L66 (-2.2559, -7.6555) -> (-2.0479, -7.4711)
  line L67 (-3.04, -3.08) -> (-3.9247, -4.849)
  line L68 (-1.0085, -6.0338) -> (-0.9672, -5.922)
  line L69 (0.9512, -3.1395) -> (1.7827, -4.9341)
  line L70 (-3.9317, -6.3858) -> (-3.8749, -6.6091)
  line L71 (-3.9661, -4.9691) -> (-3.9832, -5.0385)
  line L72 (4.5272, -3.3929) -> (4.4656, -3.2909)
  line L73 (-4.0147, -5.2265) -> (-4.026, -5.3451)
  line L74 (6.9076, -0.1898) -> (7.1126, -0.0847)
  line L75 (-1.2077, -6.44) -> (-1.1275, -6.2938)
  line L76 (-3.937, -4.8783) -> (-3.9502, -4.9158)
  line L77 (-4.0042, -5.9793) -> (-3.9743, -6.1756)
  line L78 (-3.9247, -4.849) -> (-3.928, -4.8562)
  line L79 (-3.8025, -6.8445) -> (-3.7132, -7.091)
  line L80 (-0.8862, -5.5746) -> (-0.8847, -5.5508)
  line L81 (2.789, -5.8001) -> (2.9799, -5.8978)
  line L82 (4.3557, -3.1352) -> (4.3101, -3.0801)
  line L83 (4.2268, -2.995) -> (4.2207, -2.9899)
  line L84 (4.2213, -6.3088) -> (5.0183, -5.6732)
  line L85 (1.7827, -4.9341) -> (1.7863, -4.9412)
  line L86 (2.9799, -5.8978) -> (3.1899, -5.9926)
  line L87 (-1.1275, -6.2938) -> (-1.0615, -6.158)
  line L88 (-4, -5.1242) -> (-4.0147, -5.2265)
  line L89 (4.8938, -4.3715) -> (4.841, -4.1636)
  line L90 (5.7958, -0.5287) -> (5.9139, -0.5133)
  line L91 (-0.8847, -5.5508) -> (-0.8846, -5.5429)
  line L92 (1.798, -4.962) -> (1.819, -4.9957)
  line L93 (-7.6013, 2.4745) -> (-7.5364, 2.4446)
  line L94 (-3.8749, -6.6091) -> (-3.8025, -6.8445)
  line L95 (-4.0228, -5.7975) -> (-4.0042, -5.9793)
  line L96 (-7.7679, -0.4986) -> (-7.8677, -0.5638)
  line L97 (-7.6788, 2.5149) -> (-7.6013, 2.4745)
  line L98 (2.4631, -5.6022) -> (2.6168, -5.701)
  line L99 (-7.8677, 2.6322) -> (-7.7679, 2.5671)
  line L100 (-8.0946, 2.8061) -> (-7.977, 2.7116)
  line L101 (-3.7132, -7.091) -> (-3.6058, -7.3474)
  line L102 (-3.6058, -7.3474) -> (-3.479, -7.6126)
  line L103 (-4.0316, -5.6309) -> (-4.0228, -5.7975)
  line L104 (2.0217, -5.2398) -> (2.1074, -5.3226)
  line L105 (5.0183, -5.6732) -> (5.0174, -5.3793)
  line L106 (-0.9362, -5.8235) -> (-0.914, -5.739)
  line L107 (-1.5451, -6.9306) -> (-1.4154, -6.7597)
  line L108 (-1.3033, -6.5957) -> (-1.2077, -6.44)
  line L109 (1.8507, -5.0413) -> (1.8943, -5.098)
  line L110 (-0.9141, -3.5653) -> (0.9512, -3.1395)
  line L111 (-1.4154, -6.7597) -> (-1.3033, -6.5957)
  line L112 (2.3274, -5.5052) -> (2.4631, -5.6022)
  line L113 (1.819, -4.9957) -> (1.8507, -5.0413)
  line L114 (3.1899, -5.9926) -> (3.419, -6.0827)
  line L115 (3.9349, -6.2425) -> (4.2213, -6.3088)
  line L116 (1.7863, -4.9412) -> (1.798, -4.962)
  line L117 (-0.8993, -5.669) -> (-0.8906, -5.6141)
  line L118 (-1.8605, -7.2877) -> (-1.6931, -7.1071)
  line L119 (-0.8906, -5.6141) -> (-0.8862, -5.5746)
  line L120 (3.419, -6.0827) -> (3.6674, -6.1666)
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  dimension "d213" distance = 0.25
extrude "Extrude1" sketch "Sketch4" blind 2.5
sketch "Sketch2" plane through (0, 4, 0) normal (0, 1, 0) x axis (-1, 0, 0)
  line L1 (26.4765, -9.7134) -> (26.466, -9.7093)
  line L2 (27.295, -7.7374) -> (27.3952, -7.7524)
  line L3 (27.3946, -13.6806) -> (27.7434, -13.6973)
  line L4 (29.1835, -4.4601) -> (28.9694, -4.3595)
  line L5 (26.9542, -9.9657) -> (26.8282, -9.8909)
  line L6 (28.4972, -11.204) -> (28.2608, -10.9786)
  line L7 (26.466, -9.7093) -> (25.9114, -9.5058)
  line L8 (30.35, -7.5596) -> (30.7349, -7.4743)
  line L9 (29.9258, -4.8629) -> (29.6625, -4.7108)
  line L10 (26.63, -9.7839) -> (26.559, -9.7495)
  line L11 (29.4148, -4.5768) -> (29.1835, -4.4601)
  line L12 (29.3165, -7.7294) -> (29.6403, -7.686)
  line L13 (27.664, -7.7809) -> (27.8327, -7.7917)
  line L14 (28.0349, -10.775) -> (27.8204, -10.5925)
  line L15 (28.4745, -7.7955) -> (28.7333, -7.783)
  line L16 (28.0823, -4.0334) -> (28.0057, -4.0146)
  line L17 (31.1391, -7.3726) -> (31.4457, -5.9302)
  line L18 (28.2984, -4.0969) -> (28.18, -4.0605)
  line L19 (28.4371, -4.1438) -> (28.2984, -4.0969)
  line L20 (27.8204, -10.5925) -> (27.6185, -10.4302)
  line L21 (28.238, -7.8004) -> (28.4745, -7.7955)
  line L22 (29.0141, -7.7613) -> (29.3165, -7.7294)
  line L23 (28.9971, -11.7234) -> (28.743, -11.4521)
  line L24 (27.1293, -7.7042) -> (27.1622, -7.712)
  line L25 (27.0689, -13.6558) -> (27.3946, -13.6806)
  line L26 (26.559, -9.7495) -> (26.5077, -9.7264)
  line L27 (30.4959, -5.2258) -> (30.2039, -5.0343)
  line L28 (29.6403, -7.686) -> (29.9849, -7.6298)
  line L29 (27.3952, -7.7524) -> (27.5182, -7.7673)
  line L30 (25.9114, -9.5058) -> (26.5501, -7.5399)
  line L31 (29.9849, -7.6298) -> (30.35, -7.5596)
  line L32 (31.1178, -5.6729) -> (30.8009, -5.4384)
  line L33 (28.18, -4.0605) -> (28.0823, -4.0334)
  line L34 (27.1184, -7.7013) -> (27.1293, -7.7042)
  line L35 (27.2558, -10.1629) -> (27.097, -10.056)
  line L36 (28.7732, -4.274) -> (28.5956, -4.2024)
  line L37 (26.8282, -9.8909) -> (26.72, -9.8307)
  line L38 (28.7333, -7.783) -> (29.0141, -7.7613)
  line L39 (30.2039, -5.0343) -> (29.9258, -4.8629)
  line L40 (29.2583, -12.0187) -> (28.9971, -11.7234)
  line L41 (26.5501, -7.5399) -> (27.1184, -7.7013)
  line L42 (27.43, -10.2873) -> (27.2558, -10.1629)
  line L43 (28.5093, -13.7011) -> (28.9258, -13.6857)
  line L44 (27.7434, -13.6973) -> (28.115, -13.7045)
  line L45 (26.5077, -9.7264) -> (26.4765, -9.7134)
  line L46 (28.9258, -13.6857) -> (29.5256, -12.3385)
  line L47 (27.1622, -7.712) -> (27.2173, -7.7235)
  line L48 (26.72, -9.8307) -> (26.63, -9.7839)
  line L49 (30.8009, -5.4384) -> (30.4959, -5.2258)
  line L50 (28.5956, -4.2024) -> (28.4371, -4.1438)
  line L51 (27.5182, -7.7673) -> (27.664, -7.7809)
  line L52 (27.097, -10.056) -> (26.9542, -9.9657)
  line L53 (28.024, -7.7987) -> (28.238, -7.8004)
  line L54 (21.2286, -21.2463) -> (21.1069, -20.9923)
  line L55 (24.5473, -15.6076) -> (24.4141, -15.47)
  line L56 (25.7902, -13.4548) -> (25.9992, -13.5009)
  line L57 (21.9544, -23.2809) -> (21.8404, -22.8801)
  line L58 (29.6625, -4.7108) -> (29.4148, -4.5768)
  line L59 (25.302, -13.319) -> (25.4418, -13.3625)
  line L60 (23.869, -14.9997) -> (23.3688, -14.6854)
  line L61 (24.1855, -15.2527) -> (24.0921, -15.1712)
  line L62 (21.188, -17.687) -> (21.6415, -18.0656)
  line L63 (23.8784, -15.0059) -> (23.869, -14.9997)
  line L64 (25.1848, -13.2788) -> (25.302, -13.319)
  line L65 (26.7664, -13.6241) -> (27.0689, -13.6558)
  line L66 (24.0139, -15.1068) -> (23.9516, -15.0584)
  line L67 (24.0921, -15.1712) -> (24.0139, -15.1068)
  line L68 (24.4141, -15.47) -> (24.2932, -15.352)
  line L69 (23.9516, -15.0584) -> (23.9062, -15.0251)
  line L70 (24.8464, -15.9445) -> (24.6917, -15.7655)
  line L71 (25.182, -16.3683) -> (25.0102, -16.1452)
  line L72 (24.9347, -13.1764) -> (24.9652, -13.1908)
  line L73 (25.0168, -13.2135) -> (25.0898, -13.2432)
  line L74 (25.0898, -13.2432) -> (25.1848, -13.2788)
  line L75 (24.9246, -13.1713) -> (24.9347, -13.1764)
  line L76 (24.6917, -15.7655) -> (24.5473, -15.6076)
  line L77 (30.7349, -7.4743) -> (31.1391, -7.3726)
  line L78 (25.9992, -13.5009) -> (26.2315, -13.5454)
  line L79 (25.6044, -13.4082) -> (25.7902, -13.4548)
  line L80 (24.9652, -13.1908) -> (25.0168, -13.2135)
  line L81 (24.4023, -12.8953) -> (24.9246, -13.1713)
  line L82 (26.4873, -13.5869) -> (26.7664, -13.6241)
  line L83 (25.4418, -13.3625) -> (25.6044, -13.4082)
  line L84 (23.3688, -14.6854) -> (24.4023, -12.8953)
  line L85 (23.9062, -15.0251) -> (23.8784, -15.0059)
  line L86 (25.0102, -16.1452) -> (24.8464, -15.9445)
  line L87 (25.3607, -16.6144) -> (25.182, -16.3683)
  line L88 (24.2932, -15.352) -> (24.1855, -15.2527)
  line L89 (25.545, -16.8841) -> (25.3607, -16.6144)
  line L90 (22.1076, -18.3602) -> (22.2572, -18.4387)
  line L91 (26.2315, -13.5454) -> (26.4873, -13.5869)
  line L92 (20.8743, -20.5547) -> (20.7658, -20.3702)
  line L93 (18.9109, -23.3331) -> (19.1743, -23.4851)
  line L94 (20.4718, -24.1124) -> (20.8585, -24.2677)
  line L95 (19.1743, -23.4851) -> (19.4618, -23.6402)
  line L96 (20.8585, -24.2677) -> (21.9544, -23.2809)
  line L97 (24.2893, -19.1661) -> (24.6513, -19.2505)
  line L98 (20.2599, -19.6672) -> (20.2367, -19.6426)
  line L99 (22.2572, -18.4387) -> (22.4292, -18.5228)
  line L100 (21.4764, -21.8263) -> (21.3521, -21.5242)
  line L101 (20.6642, -20.2079) -> (20.5705, -20.0673)
  line L102 (21.9799, -18.2885) -> (22.1076, -18.3602)
  line L103 (26.1201, -17.8392) -> (25.926, -17.4961)
  line L104 (23.0836, -18.797) -> (23.3489, -18.8914)
  line L105 (21.6001, -22.1528) -> (21.4764, -21.8263)
  line L106 (25.926, -17.4961) -> (25.7339, -17.1778)
  line L107 (20.1102, -23.9551) -> (20.4718, -24.1124)
  line L108 (19.4618, -23.6402) -> (19.7737, -23.7973)
  line L109 (22.624, -18.6114) -> (22.8421, -18.7032)
  line L110 (17.6972, -22.4587) -> (17.8072, -22.5554)
  line L111 (20.2288, -19.6346) -> (19.8048, -19.2231)
  line L112 (25.0377, -19.3291) -> (25.4482, -19.4006)
  line L113 (21.6415, -18.0656) -> (21.6503, -18.0726)
  line L114 (21.8404, -22.8801) -> (21.7218, -22.504)
  line L115 (19.7737, -23.7973) -> (20.1102, -23.9551)
  line L116 (26.3151, -18.2076) -> (26.1201, -17.8392)
  line L117 (25.4482, -19.4006) -> (26.3151, -18.2076)
  line L118 (21.7881, -18.1703) -> (21.8736, -18.2248)
  line L119 (20.5705, -20.0673) -> (20.4858, -19.9478)
  line L120 (17.6065, -22.3743) -> (17.6972, -22.4587)
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  point P1 (0, 0)
  point P3 (0, 0)
  coincident P1 P3
extrude "Extrude2" add sketch "Sketch2" to an object offset -0.5
as_built_joint "As-built2" OffsetX 0 OffsetY 0 OffsetZ 0 AngleZ 0
canvas "Canvas1"
canvas "Canvas2"
as_built_joint "As-built3" OffsetX 0 OffsetY 0 OffsetZ 0 AngleZ 0
sketch "Sketch3" plane through (0, 4, 0) normal (0, -1, 0) x axis (1, 0, 0)
  circle C1 centre (-26.7653, -26.7653) radius 2
  circle C2 centre (-26.7653, -26.7653) radius 2.25
  dimension "d215" diameter C1 = 4 (= "KnobRodThick")
extrude "Extrude2" add sketch "Sketch3" profile of C1 to an object offset 7.5
sketch "Sketch1" plane through (0, -8.25, 0) normal (0, -1, 0) x axis (1, 0, 0)
  line L1 (-40.1846, 22.0238) -> (-35.5682, 33.812)
  line L2 (-40.4655, -20.5361) -> (-40.4655, 20.5361)
  line L3 (-35.5682, -33.812) -> (-40.1846, -22.0238)
  line L4 (-22.8502, -40.1861) -> (-33.2529, -36.1249)
  line L5 (21.3665, -40.4655) -> (-21.3665, -40.4655)
  line L6 (33.2529, -36.1249) -> (22.8502, -40.1861)
  line L7 (40.1846, -22.0238) -> (35.5682, -33.812)
  line L8 (40.4655, 20.5361) -> (40.4655, -20.5361)
  line L9 (35.5682, 33.812) -> (40.1846, 22.0238)
  line L10 (22.8502, 40.1861) -> (33.2529, 36.1249)
  line L11 (-21.3665, 40.4655) -> (21.3665, 40.4655)
  line L12 (-33.2529, 36.1249) -> (-22.8502, 40.1861)
  circle C1 centre (-31.4309, -31.4309) radius 2.159
  circle C2 centre (36.96, 18.76) radius 1.75
  circle C3 centre (18.76, -36.96) radius 1.75
  circle C4 centre (-36.96, -18.76) radius 1.75
  circle C5 centre (-18.76, 36.96) radius 1.75
  circle C6 centre (-36.96, 18.76) radius 1.75
  circle C7 centre (-18.76, -36.96) radius 1.75
  circle C8 centre (36.96, -18.76) radius 1.75
  circle C9 centre (18.76, 36.96) radius 1.75
  circle C10 centre (31.4309, 31.4309) radius 2.159
  circle C11 centre (-31.4309, -31.4309) radius 2.159
  circle C12 centre (-31.4309, 31.4309) radius 2.159
  circle C13 centre (31.4309, -31.4309) radius 2.159
  circle C14 centre (0, 0) radius 39.6875
  arc A1 centre (-36.3855, 20.5361) radius 4.08 clockwise from (-40.4655, 20.5361) to (-40.1846, 22.0238)
  arc A2 centre (-36.3855, -20.5361) radius 4.08 clockwise from (-40.1846, -22.0238) to (-40.4655, -20.5361)
  arc A3 centre (-31.7692, -32.3242) radius 4.08 clockwise from (-33.2529, -36.1249) to (-35.5682, -33.812)
  arc A4 centre (-21.3665, -36.3855) radius 4.08 clockwise from (-21.3665, -40.4655) to (-22.8502, -40.1861)
  arc A5 centre (21.3665, -36.3855) radius 4.08 clockwise from (22.8502, -40.1861) to (21.3665, -40.4655)
  arc A6 centre (31.7692, -32.3242) radius 4.08 clockwise from (35.5682, -33.812) to (33.2529, -36.1249)
  arc A7 centre (36.3855, -20.5361) radius 4.08 clockwise from (40.4655, -20.5361) to (40.1846, -22.0238)
  arc A8 centre (36.3855, 20.5361) radius 4.08 clockwise from (40.1846, 22.0238) to (40.4655, 20.5361)
  arc A9 centre (31.7692, 32.3242) radius 4.08 clockwise from (33.2529, 36.1249) to (35.5682, 33.812)
  arc A10 centre (21.3665, 36.3855) radius 4.08 clockwise from (21.3665, 40.4655) to (22.8502, 40.1861)
  arc A11 centre (-21.3665, 36.3855) radius 4.08 clockwise from (-22.8502, 40.1861) to (-21.3665, 40.4655)
  arc A12 centre (-31.7692, 32.3242) radius 4.08 clockwise from (-35.5682, 33.812) to (-33.2529, 36.1249)
extrude "Extrude2" add sketch "Sketch1" profile of C4 C1 to an object
move "Move1"
motion_link "MotionLink1" Value1 320 Value2 70
position "Position5"
sketch "Sketch1" plane through (0, 0, 12.75) normal (0, 0, 1) x axis (-1, 0, 0)
  circle C1 centre (0, 0) radius 1.6
  circle C2 centre (0, 0) radius 3.75
  circle C3 centre (0.0079, 0.0724) radius 2
  circle C4 centre (0.0079, 0.0724) radius 2
  circle C5 centre (0.0079, 0.0724) radius 2.15
  circle C6 centre (-0.0079, -0.0724) radius 2
  point P1 (0, 0)
  point P2 (0, 0)
  point P3 (0, 0)
  coincident P1 P2
  coincident P1 P3
  dimension "d1" diameter C1 = 3.2 (= "3 mm + PressFit * 2")
  dimension "d2" diameter C2 = 7.5
  dimension "d143" = 0.15
extrude "Extrude1" new body sketch "Sketch1" profile of C2 C5 along a picked direction blind -5 bodies "Knob"
work_plane "WorkPlane1" AlongDistance 1
sketch "Sketch2" plane through (0, 0, 13.75) normal (0, 0, 1) x axis (1, 0, 0)
  circle C1 centre (0, 0) radius 6
  circle C2 centre (0, 0) radius 5
  point P1 (0, 0)
  point P2 (0, 0)
  coincident P1 P2
  dimension "d6" diameter C1 = 12
  dimension "d11_1" = -1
